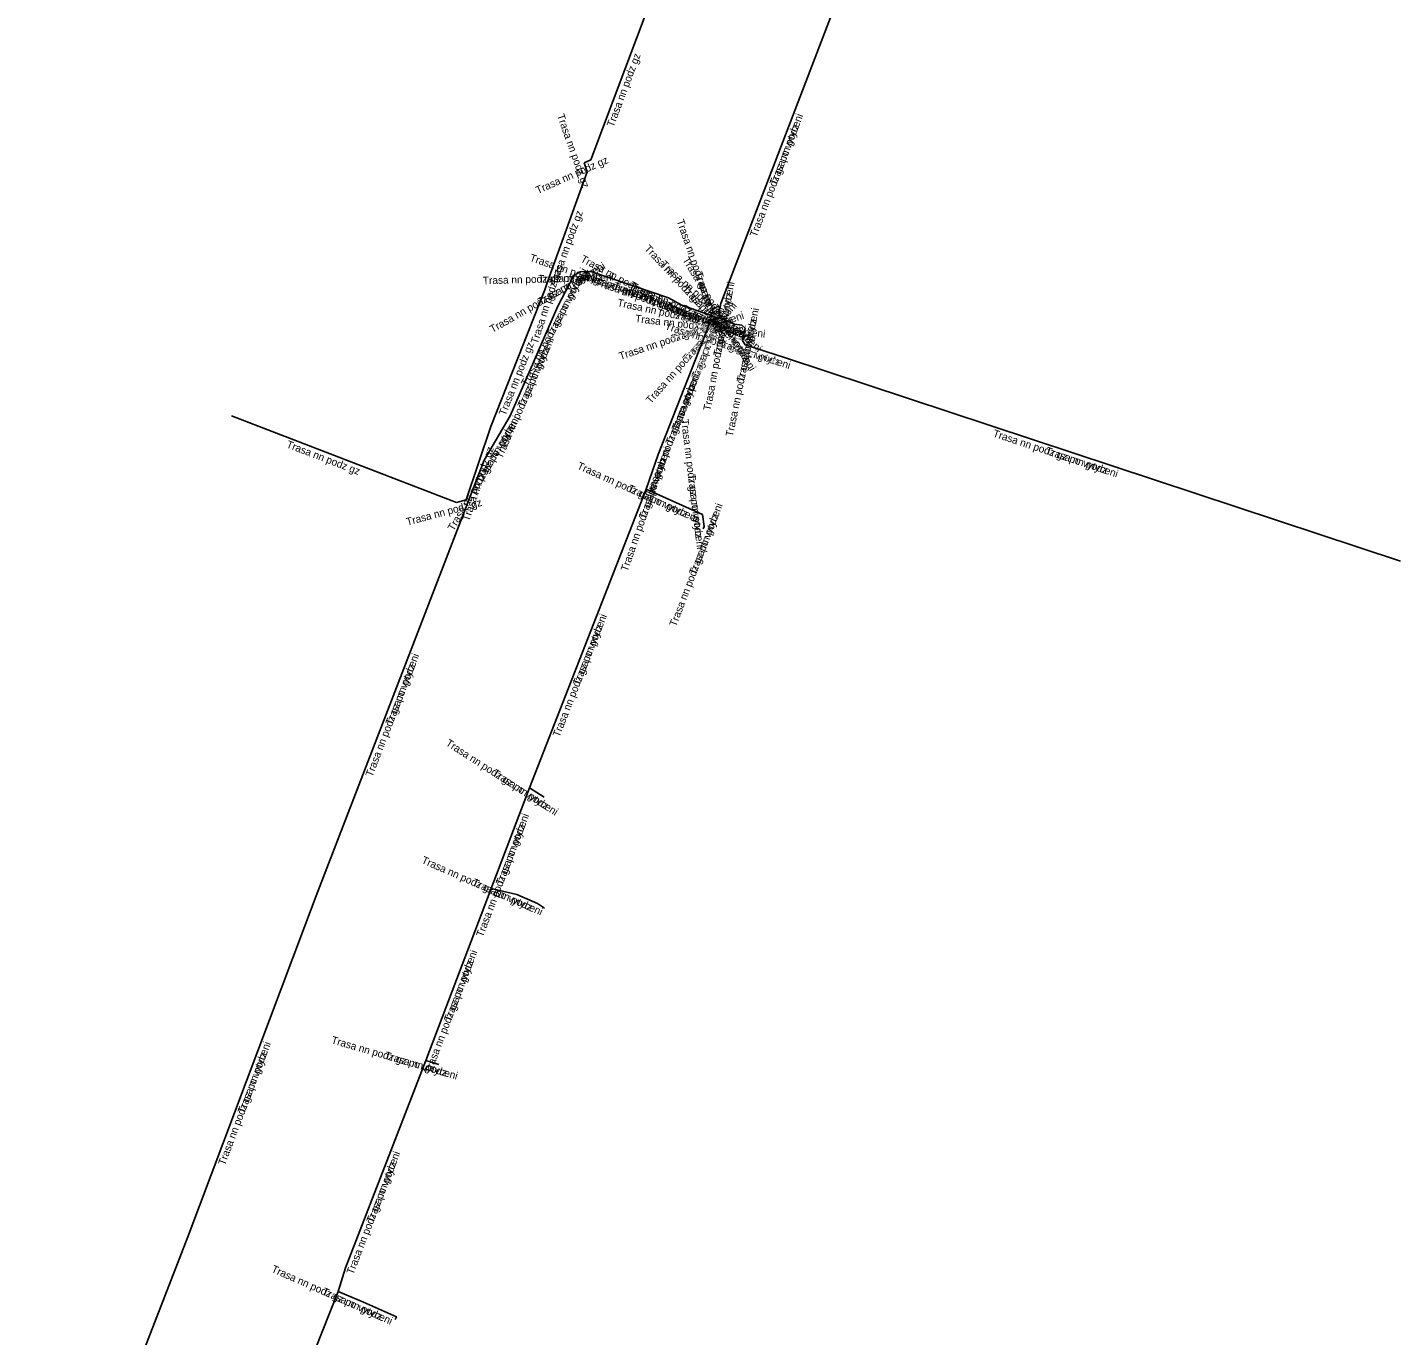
# Model space of a CAD drawing. Extents: x -644332 to -644190, y -1042435 to -1042173.
# Drawn here: x -644287.3 to -644196.1, y -1042366.5 to -1042279.6 of the extents above; entities that cross this region are included whole.
import ezdxf

# ---------------------------------------------------------------- set-up
doc = ezdxf.new("R2010")
doc.units = 0
doc.layers.add('Popiskový text - Ostatní atributy Trasy', color=7, linetype='Continuous')
doc.layers.add('Spojnice NN', color=7, linetype='Continuous')

msp = doc.modelspace()

# ---------------------------------------------------------------- linework, layer by layer
at = {"layer": 'Spojnice NN'}
for points in [[(-644245.35, -1042276.4), (-644249.86, -1042288.43)], [(-644232.82, -1042276), (-644241.24, -1042297.96)], [(-644232.82, -1042276), (-644241.24, -1042297.96)], [(-644249.86, -1042288.43), (-644250.318, -1042288.632)], [(-644250.11, -1042289.22), (-644252.75, -1042296.52)], [(-644250.318, -1042288.632), (-644250.11, -1042289.22)], [(-644251, -1042296.1), (-644250.58, -1042295.86)], [(-644251, -1042296.1), (-644250.58, -1042295.86)], [(-644250.58, -1042295.86), (-644249.86, -1042295.84)], [(-644250.58, -1042295.86), (-644249.86, -1042295.84)], [(-644249.86, -1042295.84), (-644244.72, -1042297.59)], [(-644249.86, -1042295.84), (-644244.72, -1042297.59)], [(-644252.75, -1042296.52), (-644252.92, -1042297.05)], [(-644252.06, -1042298.15), (-644251, -1042296.1)], [(-644252.06, -1042298.15), (-644251, -1042296.1)], [(-644252.92, -1042297.05), (-644256.5, -1042306.14)], [(-644243.83, -1042298.07), (-644244.72, -1042297.59)], [(-644243.83, -1042298.07), (-644244.72, -1042297.59)], [(-644255.22, -1042305.42), (-644252.06, -1042298.15)], [(-644255.22, -1042305.42), (-644252.06, -1042298.15)], [(-644242.07, -1042298.69), (-644243.83, -1042298.07)], [(-644242.07, -1042298.69), (-644243.83, -1042298.07)], [(-644241.24, -1042297.96), (-644241.36, -1042298.6)], [(-644241.24, -1042297.96), (-644241.36, -1042298.6)], [(-644241.36, -1042298.6), (-644241.28, -1042298.83)], [(-644241.36, -1042298.6), (-644241.28, -1042298.83)], [(-644241.97, -1042299.23), (-644242.44, -1042300.45)], [(-644241.97, -1042299.23), (-644242.44, -1042300.45)], [(-644241.51, -1042298.9), (-644242.07, -1042298.69)], [(-644241.51, -1042298.9), (-644242.07, -1042298.69)], [(-644241.75, -1042298.98), (-644241.97, -1042299.23)], [(-644241.75, -1042298.98), (-644241.97, -1042299.23)], [(-644241.51, -1042298.9), (-644241.75, -1042298.98)], [(-644241.51, -1042298.9), (-644241.75, -1042298.98)], [(-644241.14, -1042298.98), (-644241.51, -1042298.9)], [(-644241.14, -1042298.98), (-644241.51, -1042298.9)], [(-644241.28, -1042298.83), (-644241.14, -1042298.98)], [(-644241.28, -1042298.83), (-644241.14, -1042298.98)], [(-644241.14, -1042298.98), (-644240.32, -1042299.34)], [(-644241.14, -1042298.98), (-644240.32, -1042299.34)], [(-644240.32, -1042299.34), (-644239.849, -1042299.396)], [(-644240.32, -1042299.34), (-644239.849, -1042299.396)], [(-644239.849, -1042299.396), (-644239.62, -1042299.6)], [(-644239.849, -1042299.396), (-644239.62, -1042299.6)], [(-644242.44, -1042300.45), (-644245.4, -1042307.99)], [(-644242.44, -1042300.45), (-644245.4, -1042307.99)], [(-644239.62, -1042299.6), (-644239.79, -1042300.43)], [(-644239.62, -1042299.6), (-644239.79, -1042300.43)], [(-644239.79, -1042300.43), (-644239.62, -1042300.71)], [(-644239.79, -1042300.43), (-644239.62, -1042300.71)], [(-644239.62, -1042300.71), (-644236.94, -1042301.57)], [(-644239.62, -1042300.71), (-644236.94, -1042301.57)], [(-644236.94, -1042301.57), (-644196.1, -1042315.08)], [(-644236.94, -1042301.57), (-644196.1, -1042315.08)], [(-644258.78, -1042311.18), (-644273.74, -1042305.43)], [(-644256.95, -1042308.37), (-644255.22, -1042305.42)], [(-644256.95, -1042308.37), (-644255.22, -1042305.42)], [(-644256.5, -1042306.14), (-644258.14, -1042311.01)], [(-644268.11, -1042337.31), (-644256.95, -1042308.37)], [(-644268.11, -1042337.31), (-644256.95, -1042308.37)], [(-644245.4, -1042307.99), (-644246.2, -1042310.29)], [(-644245.4, -1042307.99), (-644246.2, -1042310.29)], [(-644246.2, -1042310.29), (-644253.95, -1042330.13)], [(-644246.2, -1042310.29), (-644253.95, -1042330.13)], [(-644246.2, -1042310.29), (-644242.45, -1042311.98)], [(-644246.2, -1042310.29), (-644242.45, -1042311.98)], [(-644258.14, -1042311.01), (-644258.78, -1042311.18)], [(-644242.45, -1042311.98), (-644242.35, -1042312.79)], [(-644242.45, -1042311.98), (-644242.35, -1042312.79)], [(-644242.402, -1042312.926), (-644242.35, -1042312.79)], [(-644242.402, -1042312.926), (-644242.35, -1042312.79)], [(-644253.95, -1042330.13), (-644256.49, -1042336.82)], [(-644253.95, -1042330.13), (-644256.49, -1042336.82)], [(-644253.95, -1042330.13), (-644252.963, -1042330.768)], [(-644253.95, -1042330.13), (-644252.963, -1042330.768)], [(-644256.49, -1042336.82), (-644260.83, -1042348.26)], [(-644256.49, -1042336.82), (-644260.83, -1042348.26)], [(-644256.49, -1042336.82), (-644254.79, -1042337.22), (-644253.41, -1042337.83), (-644252.94, -1042338.13)], [(-644256.49, -1042336.82), (-644254.79, -1042337.22), (-644253.41, -1042337.83), (-644252.94, -1042338.13)], [(-644276.63, -1042359.96), (-644268.11, -1042337.31)], [(-644276.63, -1042359.96), (-644268.11, -1042337.31)], [(-644260.83, -1042348.26), (-644266.16, -1042362.03), (-644266.64, -1042363.59)], [(-644260.83, -1042348.26), (-644266.16, -1042362.03), (-644266.64, -1042363.59)], [(-644260.83, -1042348.26), (-644259.97, -1042348.51)], [(-644260.83, -1042348.26), (-644259.97, -1042348.51)], [(-644287.28, -1042387.44), (-644276.63, -1042359.96)], [(-644287.28, -1042387.44), (-644276.63, -1042359.96)], [(-644266.64, -1042363.59), (-644270.85, -1042374.21)], [(-644266.64, -1042363.59), (-644270.85, -1042374.21)], [(-644266.64, -1042363.59), (-644264.96, -1042364.31), (-644262.78, -1042365.28), (-644262.865, -1042365.457)], [(-644266.64, -1042363.59), (-644264.96, -1042364.31), (-644262.78, -1042365.28), (-644262.865, -1042365.457)]]:
    msp.add_lwpolyline(points, dxfattribs=at)

# ---------------------------------------------------------------- texts
at = {"layer": 'Popiskový text - Ostatní atributy Trasy'}
for s, rotation, p in [('Trasa nn podz gz', 69.44917, (-644248.363, -1042286.289)), ('Trasa nn podz gz', 289.4808, (-644252.125, -1042285.472)), ('Trasa nn podz gz po vytyceni', 69.02196, (-644238.87, -1042293.592)), ('Trasa nn podz', 69.02196, (-644237.55, -1042290.152)), ('Trasa nn podz gz', 23.79978, (-644253.39, -1042290.697)), ('Trasa nn podz gz', 70.11779, (-644252.143, -1042296.753)), ('Trasa nn podz gz po vytyceni', 289.17901, (-644244.179, -1042292.475)), ('Trasa nn podz gz po vytyceni', 313.02507, (-644246.347, -1042294.354)), ('Trasa nn podz gz po vytyceni', 341.19799, (-644253.968, -1042295.128)), ('Trasa nn podz gz po vytyceni', 331.66087, (-644250.597, -1042295.159)), ('Trasa nn podz gz po vytyceni', 301.26373, (-644243.807, -1042295.067)), ('Trasa nn podz gz po vytyceni', 29.74488, (-644256.4, -1042299.934)), ('Trasa nn podz gz po vytyceni', 62.65773, (-644254.091, -1042303.493)), ('Trasa nn podz gz', 72.21611, (-644253.405, -1042300.691)), ('Trasa nn podz', 29.74488, (-644253.201, -1042298.106)), ('Trasa nn podz', 341.19799, (-644250.479, -1042296.316)), ('Trasa nn podz gz po vytyceni', 318.34315, (-644245.271, -1042295.442)), ('Trasa nn podz', 289.17901, (-644242.968, -1042295.955)), ('Trasa nn podz gz po vytyceni', 1.59114, (-644257.032, -1042296.69)), ('Trasa nn podz', 1.59114, (-644253.348, -1042296.587)), ('Trasa nn podz', 62.65773, (-644252.399, -1042300.22)), ('Trasa nn podz gz po vytyceni', 340.59403, (-644249.611, -1042296.723)), ('Trasa nn podz gz po vytyceni', 339.44395, (-644248.415, -1042297.005)), ('Trasa nn podz', 331.66087, (-644247.354, -1042296.908)), ('Trasa nn podz gz po vytyceni', 336.29735, (-644247.248, -1042297.008)), ('Trasa nn podz', 313.02507, (-644243.832, -1042297.047)), ('Trasa nn podz gz po vytyceni', 79.38034, (-644241.92, -1042305.116)), ('Trasa nn podz gz po vytyceni', 347.79953, (-644248.141, -1042298.131)), ('Trasa nn podz', 340.59403, (-644246.135, -1042297.947)), ('Trasa nn podz', 318.34315, (-644242.518, -1042297.892)), ('Trasa nn podz', 79.38034, (-644241.241, -1042301.494)), ('Trasa nn podz gz po vytyceni', 18.43495, (-644247.907, -1042301.717)), ('Trasa nn podz gz po vytyceni', 48.65222, (-644245.886, -1042304.664)), ('Trasa nn podz', 339.44395, (-644244.965, -1042298.299)), ('Trasa nn podz gz po vytyceni', 68.93102, (-644244.055, -1042306.45)), ('Trasa nn podz', 347.79953, (-644244.539, -1042298.91)), ('Trasa nn podz', 48.65222, (-644243.452, -1042301.897)), ('Trasa nn podz', 336.29735, (-644243.874, -1042298.49)), ('Trasa nn podz', 301.26373, (-644241.894, -1042298.217)), ('Trasa nn podz gz po vytyceni', 78.42481, (-644240.439, -1042306.839)), ('Trasa nn podz gz po vytyceni', 353.16322, (-644246.946, -1042299.2)), ('Trasa nn podz gz po vytyceni', 342.2088, (-644244.984, -1042299.671)), ('Trasa nn podz', 18.43495, (-644244.411, -1042300.552)), ('Trasa nn podz', 353.16322, (-644243.287, -1042299.639)), ('Trasa nn podz', 68.93102, (-644242.73, -1042303.011)), ('Trasa nn podz', 78.42481, (-644239.7, -1042303.229)), ('Trasa nn podz gz po vytyceni', 66.5072, (-644255.767, -1042308.31)), ('Trasa nn podz', 342.2088, (-644241.475, -1042300.797)), ('Trasa nn podz gz', 68.50353, (-644255.532, -1042305.456)), ('Trasa nn podz', 66.5072, (-644254.298, -1042304.93)), ('Trasa nn podz gz po vytyceni', 68.56637, (-644245.812, -1042310.817)), ('Trasa nn podz', 68.56637, (-644244.466, -1042307.387)), ('Trasa nn podz gz po vytyceni', 59.61091, (-644258.981, -1042313.117)), ('Trasa nn podz gz po vytyceni', 277.03794, (-644243.882, -1042305.683)), ('Trasa nn podz', 59.61091, (-644257.117, -1042309.939)), ('Trasa nn podz gz po vytyceni', 341.69562, (-644223.211, -1042306.796)), ('Trasa nn podz gz', 338.97532, (-644270.128, -1042307.514)), ('Trasa nn podz gz', 71.38876, (-644257.947, -1042312.473)), ('Trasa nn podz gz po vytyceni', 70.82099, (-644247.431, -1042315.807)), ('Trasa nn podz', 341.69562, (-644219.713, -1042307.954)), ('Trasa nn podz gz po vytyceni', 335.7405, (-644250.821, -1042308.921)), ('Trasa nn podz', 70.82099, (-644246.22, -1042312.326)), ('Trasa nn podz', 277.03794, (-644243.431, -1042309.341)), ('Trasa nn podz', 335.7405, (-644247.461, -1042310.435)), ('Trasa nn podz gz', 14.87568, (-644262.056, -1042312.723)), ('Trasa nn podz gz po vytyceni', 69.0755, (-644244.209, -1042319.472)), ('Trasa nn podz', 69.0755, (-644242.893, -1042316.03)), ('Trasa nn podz gz po vytyceni', 68.66314, (-644251.955, -1042326.811)), ('Trasa nn podz', 68.66314, (-644250.614, -1042323.379)), ('Trasa nn podz gz po vytyceni', 68.91209, (-644264.382, -1042329.449)), ('Trasa nn podz', 68.91209, (-644263.056, -1042326.011)), ('Trasa nn podz gz po vytyceni', 327.12124, (-644259.548, -1042327.286)), ('Trasa nn podz', 327.12124, (-644256.453, -1042329.286)), ('Trasa nn podz gz po vytyceni', 69.20968, (-644257.038, -1042340.094)), ('Trasa nn podz', 69.20968, (-644255.73, -1042336.648)), ('Trasa nn podz gz po vytyceni', 336.15318, (-644261.155, -1042335.117)), ('Trasa nn podz', 336.15318, (-644257.785, -1042336.607)), ('Trasa nn podz gz po vytyceni', 69.22473, (-644260.476, -1042349.159)), ('Trasa nn podz', 69.22473, (-644259.169, -1042345.714)), ('Trasa nn podz gz po vytyceni', 343.79098, (-644267.143, -1042347.102)), ('Trasa nn podz gz po vytyceni', 69.38576, (-644274.168, -1042355.259)), ('Trasa nn podz', 69.38576, (-644272.87, -1042351.81)), ('Trasa nn podz', 343.79098, (-644263.604, -1042348.13)), ('Trasa nn podz gz po vytyceni', 68.83991, (-644265.65, -1042362.512)), ('Trasa nn podz', 68.83991, (-644264.32, -1042359.076)), ('Trasa nn podz gz po vytyceni', 336.01313, (-644271.122, -1042362.28)), ('Trasa nn podz', 336.01313, (-644267.755, -1042363.778))]:
    msp.add_text(s, height=0.5, rotation=rotation, dxfattribs=at).set_placement(p)

doc.saveas('drawing.dxf')
